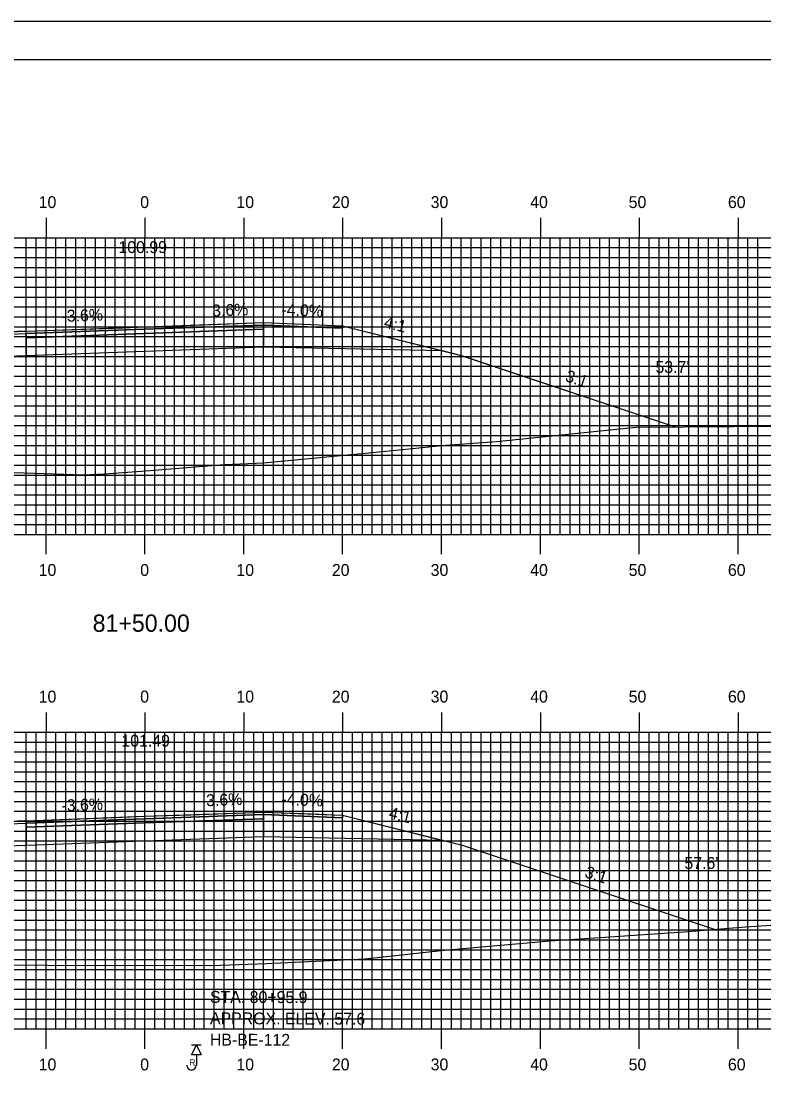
# Model space of a CAD drawing. Extents: x 1762578 to 1762921, y 442591 to 442811.
# Drawn here: x 1762731.3 to 1762806.4, y 442702.5 to 442810.5 of the extents above; entities that cross this region are included whole.
import ezdxf

# ---------------------------------------------------------------- set-up
doc = ezdxf.new("R2010")
doc.units = 0
for name, color, linetype in [('ANNOTATION', 7, 'Continuous'), ('BORDER', 7, 'Continuous'), ('BORING - REFUSAL', 7, 'Continuous'), ('D_Roadway_Centerline', 7, 'Continuous'), ('D_Roadway_Centerline_Text', 7, 'Continuous'), ('D_Roadway_Edge_Shoulder', 7, 'Continuous'), ('D_Roadway_Edge_TW', 7, 'Continuous'), ('D_Roadway_Pavement', 7, 'Continuous'), ('D_Roadway_SlopeLines', 7, 'Continuous'), ('D_Roadway_SubGrade', 7, 'Continuous'), ('D_Text_Standard', 7, 'Continuous'), ('H_V ANNOTATION', 7, 'Continuous'), ('MAJOR', 7, 'Continuous'), ('MINOR', 7, 'Continuous'), ('PLOT BOUNDARY', 7, 'Continuous'), ('S_Roadway_Centerline', 7, 'Continuous')]:
    doc.layers.add(name, color=color, linetype=linetype)

msp = doc.modelspace()

# ---------------------------------------------------------------- linework, layer by layer
at = {"layer": 'BORDER'}
msp.add_lwpolyline([(1762594.18, 442596.67), (1762914.18, 442596.67), (1762914.18, 442806.67), (1762594.18, 442806.67)], close=True, dxfattribs=at)
at = {"layer": 'BORING - REFUSAL'}
for p, q in [((1762749.46, 442707.01), (1762748.5, 442707.01)), ((1762748.98, 442706.05), (1762748.98, 442704.99))]:
    msp.add_line(p, q, dxfattribs=at)
msp.add_lwpolyline([(1762748.98, 442707.01), (1762749.46, 442706.05), (1762748.5, 442706.05)], close=True, dxfattribs=at)
msp.add_arc((1762748.49, 442704.99), 0.485, 180, 0, dxfattribs=at)
at = {"layer": 'D_Roadway_Centerline'}
for points in [[(1762679.23, 442765.05), (1762679.24, 442765.05), (1762683.25, 442766.39), (1762711.78, 442775.9), (1762712.06, 442775.97), (1762712.25, 442776.02), (1762712.25, 442776.02), (1762719.64, 442777.87), (1762723.78, 442778.9), (1762725.57, 442778.97), (1762731.78, 442779.22), (1762741.55, 442779.57), (1762743.78, 442779.66), (1762743.78, 442779.66), (1762749.62, 442779.87), (1762755.78, 442780.09), (1762755.78, 442780.09), (1762763.78, 442779.77), (1762763.78, 442779.77), (1762772.96, 442777.47), (1762773.95, 442777.22), (1762775.78, 442776.77), (1762775.79, 442776.76), (1762797.43, 442769.55)], [(1762724.97, 442729.45), (1762731.78, 442729.72), (1762731.78, 442729.72), (1762739.96, 442730.02), (1762743.78, 442730.16), (1762743.78, 442730.16), (1762748.39, 442730.32), (1762755.78, 442730.59), (1762755.78, 442730.59), (1762759.75, 442730.43), (1762763.78, 442730.27), (1762763.78, 442730.27), (1762763.78, 442730.27), (1762768.03, 442729.2), (1762773.95, 442727.72), (1762773.95, 442727.72), (1762775.78, 442727.27), (1762775.78, 442727.27), (1762801.37, 442718.74)]]:
    msp.add_lwpolyline(points, dxfattribs=at)
at = {"layer": 'D_Roadway_Edge_Shoulder'}
for points in [[(1762755.78, 442780.09), (1762763.78, 442779.77), (1762763.78, 442779.52), (1762755.78, 442779.84)], [(1762731.78, 442779.22), (1762723.78, 442778.9), (1762723.78, 442778.65), (1762731.78, 442778.97)], [(1762731.78, 442729.72), (1762723.78, 442729.4), (1762723.78, 442729.15), (1762731.78, 442729.47)], [(1762755.78, 442730.59), (1762763.78, 442730.27), (1762763.78, 442730.02), (1762755.78, 442730.34)]]:
    msp.add_lwpolyline(points, close=True, dxfattribs=at)
at = {"layer": 'D_Roadway_Edge_TW'}
for points in [[(1762731.78, 442778.97), (1762731.78, 442779.22), (1762743.78, 442779.66), (1762755.78, 442780.09), (1762755.78, 442779.84), (1762743.78, 442779.41)], [(1762755.78, 442780.09), (1762755.78, 442780.09), (1762755.78, 442779.84), (1762755.78, 442779.84)], [(1762731.78, 442729.47), (1762731.78, 442729.72), (1762743.78, 442730.16), (1762755.78, 442730.59), (1762755.78, 442730.34), (1762743.78, 442729.91)], [(1762755.78, 442730.59), (1762755.78, 442730.59), (1762755.78, 442730.34), (1762755.78, 442730.34)]]:
    msp.add_lwpolyline(points, close=True, dxfattribs=at)
at = {"layer": 'D_Roadway_Pavement'}
for points in [[(1762731.78, 442778.56), (1762731.78, 442778.97), (1762743.78, 442779.41), (1762755.78, 442779.84), (1762755.78, 442779.42), (1762743.78, 442778.99)], [(1762755.78, 442779.84), (1762755.78, 442779.84), (1762755.78, 442779.42), (1762755.78, 442779.42)], [(1762731.78, 442729.06), (1762731.78, 442729.47), (1762743.78, 442729.91), (1762755.78, 442730.34), (1762755.78, 442729.92), (1762743.78, 442729.49)], [(1762755.78, 442730.34), (1762755.78, 442730.34), (1762755.78, 442729.92), (1762755.78, 442729.92)]]:
    msp.add_lwpolyline(points, close=True, dxfattribs=at)
for points in [[(1762755.78, 442779.84), (1762755.78, 442779.42)], [(1762755.78, 442779.84), (1762755.78, 442779.42)], [(1762755.78, 442779.84), (1762755.78, 442779.42)], [(1762755.78, 442730.34), (1762755.78, 442729.92)], [(1762755.78, 442730.34), (1762755.78, 442729.92)], [(1762755.78, 442730.34), (1762755.78, 442729.92)]]:
    msp.add_lwpolyline(points, dxfattribs=at)
at = {"layer": 'D_Roadway_SlopeLines'}
for points in [[(1762763.78, 442779.77), (1762775.78, 442776.77), (1762797.43, 442769.55)], [(1762763.78, 442730.27), (1762775.78, 442727.27), (1762801.37, 442718.74)]]:
    msp.add_lwpolyline(points, dxfattribs=at)
at = {"layer": 'D_Roadway_SubGrade'}
for points in [[(1762731.78, 442776.72), (1762731.78, 442778.56), (1762743.78, 442778.99), (1762755.78, 442779.42), (1762755.78, 442777.59), (1762743.78, 442777.16)], [(1762755.78, 442779.42), (1762755.78, 442779.84), (1762763.78, 442779.52), (1762763.78, 442779.77), (1762773.95, 442777.22), (1762755.78, 442777.59)], [(1762755.78, 442779.42), (1762755.78, 442779.42), (1762755.78, 442777.59), (1762755.78, 442777.59)], [(1762723.78, 442778.65), (1762731.78, 442778.97), (1762731.78, 442778.56), (1762731.78, 442776.72), (1762712.25, 442776.02), (1762723.78, 442778.9)], [(1762731.78, 442727.22), (1762731.78, 442729.06), (1762743.78, 442729.49), (1762755.78, 442729.92), (1762755.78, 442728.09), (1762743.78, 442727.66)], [(1762755.78, 442729.92), (1762755.78, 442730.34), (1762763.78, 442730.02), (1762763.78, 442730.27), (1762773.95, 442727.72), (1762755.78, 442728.09)], [(1762755.78, 442729.92), (1762755.78, 442729.92), (1762755.78, 442728.09), (1762755.78, 442728.09)], [(1762723.78, 442729.15), (1762731.78, 442729.47), (1762731.78, 442729.06), (1762731.78, 442727.22), (1762712.25, 442726.52), (1762723.78, 442729.4)]]:
    msp.add_lwpolyline(points, close=True, dxfattribs=at)
at = {"layer": 'MAJOR'}
for p, q in [((1762733.78, 442790.67), (1762733.78, 442788.67)), ((1762743.78, 442790.67), (1762743.78, 442788.67)), ((1762753.78, 442790.67), (1762753.78, 442788.67)), ((1762763.78, 442790.67), (1762763.78, 442788.67)), ((1762773.78, 442790.67), (1762773.78, 442788.67)), ((1762783.78, 442790.67), (1762783.78, 442788.67)), ((1762793.78, 442790.67), (1762793.78, 442788.67)), ((1762803.78, 442790.67), (1762803.78, 442788.67)), ((1762603.78, 442788.67), (1762883.78, 442788.67)), ((1762603.78, 442788.67), (1762883.78, 442788.67)), ((1762733.78, 442758.67), (1762733.78, 442788.67)), ((1762743.78, 442758.67), (1762743.78, 442788.67)), ((1762753.78, 442758.67), (1762753.78, 442788.67)), ((1762763.78, 442758.67), (1762763.78, 442788.67)), ((1762773.78, 442758.67), (1762773.78, 442788.67)), ((1762783.78, 442758.67), (1762783.78, 442788.67)), ((1762793.78, 442758.67), (1762793.78, 442788.67)), ((1762803.78, 442758.67), (1762803.78, 442788.67)), ((1762603.78, 442783.67), (1762883.78, 442783.67)), ((1762603.78, 442778.67), (1762883.78, 442778.67)), ((1762603.78, 442773.67), (1762883.78, 442773.67)), ((1762603.78, 442768.67), (1762883.78, 442768.67)), ((1762603.78, 442763.67), (1762883.78, 442763.67)), ((1762603.78, 442758.67), (1762883.78, 442758.67)), ((1762603.78, 442758.67), (1762883.78, 442758.67)), ((1762733.78, 442756.66), (1762733.78, 442758.67)), ((1762743.78, 442756.66), (1762743.78, 442758.67)), ((1762753.78, 442756.66), (1762753.78, 442758.67)), ((1762763.78, 442756.66), (1762763.78, 442758.67)), ((1762773.78, 442756.66), (1762773.78, 442758.67)), ((1762783.78, 442756.66), (1762783.78, 442758.67)), ((1762793.78, 442756.66), (1762793.78, 442758.67)), ((1762803.78, 442756.66), (1762803.78, 442758.67)), ((1762733.78, 442740.67), (1762733.78, 442738.67)), ((1762743.78, 442740.67), (1762743.78, 442738.67)), ((1762753.78, 442740.67), (1762753.78, 442738.67)), ((1762763.78, 442740.67), (1762763.78, 442738.67)), ((1762773.78, 442740.67), (1762773.78, 442738.67)), ((1762783.78, 442740.67), (1762783.78, 442738.67)), ((1762793.78, 442740.67), (1762793.78, 442738.67)), ((1762803.78, 442740.67), (1762803.78, 442738.67)), ((1762603.78, 442738.67), (1762883.78, 442738.67)), ((1762603.78, 442738.67), (1762883.78, 442738.67)), ((1762733.78, 442708.67), (1762733.78, 442738.67)), ((1762743.78, 442708.67), (1762743.78, 442738.67)), ((1762753.78, 442708.67), (1762753.78, 442738.67)), ((1762763.78, 442708.67), (1762763.78, 442738.67)), ((1762773.78, 442708.67), (1762773.78, 442738.67)), ((1762783.78, 442708.67), (1762783.78, 442738.67)), ((1762793.78, 442708.67), (1762793.78, 442738.67)), ((1762803.78, 442708.67), (1762803.78, 442738.67)), ((1762603.78, 442733.67), (1762883.78, 442733.67)), ((1762603.78, 442728.67), (1762883.78, 442728.67)), ((1762603.78, 442723.67), (1762883.78, 442723.67)), ((1762603.78, 442718.67), (1762883.78, 442718.67)), ((1762603.78, 442713.67), (1762883.78, 442713.67)), ((1762603.78, 442708.67), (1762883.78, 442708.67)), ((1762603.78, 442708.67), (1762883.78, 442708.67)), ((1762733.78, 442706.66), (1762733.78, 442708.67)), ((1762743.78, 442706.66), (1762743.78, 442708.67)), ((1762753.78, 442706.66), (1762753.78, 442708.67)), ((1762763.78, 442706.66), (1762763.78, 442708.67)), ((1762773.78, 442706.66), (1762773.78, 442708.67)), ((1762783.78, 442706.66), (1762783.78, 442708.67)), ((1762793.78, 442706.66), (1762793.78, 442708.67)), ((1762803.78, 442706.66), (1762803.78, 442708.67))]:
    msp.add_line(p, q, dxfattribs=at)
at = {"layer": 'MINOR'}
for p, q in [((1762731.78, 442758.67), (1762731.78, 442788.67)), ((1762732.78, 442758.67), (1762732.78, 442788.67)), ((1762734.78, 442758.67), (1762734.78, 442788.67)), ((1762735.78, 442758.67), (1762735.78, 442788.67)), ((1762736.78, 442758.67), (1762736.78, 442788.67)), ((1762737.78, 442758.67), (1762737.78, 442788.67)), ((1762738.78, 442758.67), (1762738.78, 442788.67)), ((1762739.78, 442758.67), (1762739.78, 442788.67)), ((1762740.78, 442758.67), (1762740.78, 442788.67)), ((1762741.78, 442758.67), (1762741.78, 442788.67)), ((1762742.78, 442758.67), (1762742.78, 442788.67)), ((1762744.78, 442758.67), (1762744.78, 442788.67)), ((1762745.78, 442758.67), (1762745.78, 442788.67)), ((1762746.78, 442758.67), (1762746.78, 442788.67)), ((1762747.78, 442758.67), (1762747.78, 442788.67)), ((1762748.78, 442758.67), (1762748.78, 442788.67)), ((1762749.78, 442758.67), (1762749.78, 442788.67)), ((1762750.78, 442758.67), (1762750.78, 442788.67)), ((1762751.78, 442758.67), (1762751.78, 442788.67)), ((1762752.78, 442758.67), (1762752.78, 442788.67)), ((1762754.78, 442758.67), (1762754.78, 442788.67)), ((1762755.78, 442758.67), (1762755.78, 442788.67)), ((1762756.78, 442758.67), (1762756.78, 442788.67)), ((1762757.78, 442758.67), (1762757.78, 442788.67)), ((1762758.78, 442758.67), (1762758.78, 442788.67)), ((1762759.78, 442758.67), (1762759.78, 442788.67)), ((1762760.78, 442758.67), (1762760.78, 442788.67)), ((1762761.78, 442758.67), (1762761.78, 442788.67)), ((1762762.78, 442758.67), (1762762.78, 442788.67)), ((1762764.78, 442758.67), (1762764.78, 442788.67)), ((1762765.78, 442758.67), (1762765.78, 442788.67)), ((1762766.78, 442758.67), (1762766.78, 442788.67)), ((1762767.78, 442758.67), (1762767.78, 442788.67)), ((1762768.78, 442758.67), (1762768.78, 442788.67)), ((1762769.78, 442758.67), (1762769.78, 442788.67)), ((1762770.78, 442758.67), (1762770.78, 442788.67)), ((1762771.78, 442758.67), (1762771.78, 442788.67)), ((1762772.78, 442758.67), (1762772.78, 442788.67)), ((1762774.78, 442758.67), (1762774.78, 442788.67)), ((1762775.78, 442758.67), (1762775.78, 442788.67)), ((1762776.78, 442758.67), (1762776.78, 442788.67)), ((1762777.78, 442758.67), (1762777.78, 442788.67)), ((1762778.78, 442758.67), (1762778.78, 442788.67)), ((1762779.78, 442758.67), (1762779.78, 442788.67)), ((1762780.78, 442758.67), (1762780.78, 442788.67)), ((1762781.78, 442758.67), (1762781.78, 442788.67)), ((1762782.78, 442758.67), (1762782.78, 442788.67)), ((1762784.78, 442758.67), (1762784.78, 442788.67)), ((1762785.78, 442758.67), (1762785.78, 442788.67)), ((1762786.78, 442758.67), (1762786.78, 442788.67)), ((1762787.78, 442758.67), (1762787.78, 442788.67)), ((1762788.78, 442758.67), (1762788.78, 442788.67)), ((1762789.78, 442758.67), (1762789.78, 442788.67)), ((1762790.78, 442758.67), (1762790.78, 442788.67)), ((1762791.78, 442758.67), (1762791.78, 442788.67)), ((1762792.78, 442758.67), (1762792.78, 442788.67)), ((1762794.78, 442758.67), (1762794.78, 442788.67)), ((1762795.78, 442758.67), (1762795.78, 442788.67)), ((1762796.78, 442758.67), (1762796.78, 442788.67)), ((1762797.78, 442758.67), (1762797.78, 442788.67)), ((1762798.78, 442758.67), (1762798.78, 442788.67)), ((1762799.78, 442758.67), (1762799.78, 442788.67)), ((1762800.78, 442758.67), (1762800.78, 442788.67)), ((1762801.78, 442758.67), (1762801.78, 442788.67)), ((1762802.78, 442758.67), (1762802.78, 442788.67)), ((1762804.78, 442758.67), (1762804.78, 442788.67)), ((1762805.78, 442758.67), (1762805.78, 442788.67)), ((1762603.78, 442787.67), (1762883.78, 442787.67)), ((1762603.78, 442786.67), (1762883.78, 442786.67)), ((1762603.78, 442785.67), (1762883.78, 442785.67)), ((1762603.78, 442784.67), (1762883.78, 442784.67)), ((1762603.78, 442782.67), (1762883.78, 442782.67)), ((1762603.78, 442781.67), (1762883.78, 442781.67)), ((1762603.78, 442780.67), (1762883.78, 442780.67)), ((1762603.78, 442779.67), (1762883.78, 442779.67)), ((1762603.78, 442777.67), (1762883.78, 442777.67)), ((1762603.78, 442776.67), (1762883.78, 442776.67)), ((1762603.78, 442775.67), (1762883.78, 442775.67)), ((1762603.78, 442774.67), (1762883.78, 442774.67)), ((1762603.78, 442772.67), (1762883.78, 442772.67)), ((1762603.78, 442771.67), (1762883.78, 442771.67)), ((1762603.78, 442770.67), (1762883.78, 442770.67)), ((1762603.78, 442769.67), (1762883.78, 442769.67)), ((1762603.78, 442767.67), (1762883.78, 442767.67)), ((1762603.78, 442766.67), (1762883.78, 442766.67)), ((1762603.78, 442765.67), (1762883.78, 442765.67)), ((1762603.78, 442764.67), (1762883.78, 442764.67)), ((1762603.78, 442762.67), (1762883.78, 442762.67)), ((1762603.78, 442761.67), (1762883.78, 442761.67)), ((1762603.78, 442760.67), (1762883.78, 442760.67)), ((1762603.78, 442759.67), (1762883.78, 442759.67)), ((1762731.78, 442708.67), (1762731.78, 442738.67)), ((1762732.78, 442708.67), (1762732.78, 442738.67)), ((1762734.78, 442708.67), (1762734.78, 442738.67)), ((1762735.78, 442708.67), (1762735.78, 442738.67)), ((1762736.78, 442708.67), (1762736.78, 442738.67)), ((1762737.78, 442708.67), (1762737.78, 442738.67)), ((1762738.78, 442708.67), (1762738.78, 442738.67)), ((1762739.78, 442708.67), (1762739.78, 442738.67)), ((1762740.78, 442708.67), (1762740.78, 442738.67)), ((1762741.78, 442708.67), (1762741.78, 442738.67)), ((1762742.78, 442708.67), (1762742.78, 442738.67)), ((1762744.78, 442708.67), (1762744.78, 442738.67)), ((1762745.78, 442708.67), (1762745.78, 442738.67)), ((1762746.78, 442708.67), (1762746.78, 442738.67)), ((1762747.78, 442708.67), (1762747.78, 442738.67)), ((1762748.78, 442708.67), (1762748.78, 442738.67)), ((1762749.78, 442708.67), (1762749.78, 442738.67)), ((1762750.78, 442708.67), (1762750.78, 442738.67)), ((1762751.78, 442708.67), (1762751.78, 442738.67)), ((1762752.78, 442708.67), (1762752.78, 442738.67)), ((1762754.78, 442708.67), (1762754.78, 442738.67)), ((1762755.78, 442708.67), (1762755.78, 442738.67)), ((1762756.78, 442708.67), (1762756.78, 442738.67)), ((1762757.78, 442708.67), (1762757.78, 442738.67)), ((1762758.78, 442708.67), (1762758.78, 442738.67)), ((1762759.78, 442708.67), (1762759.78, 442738.67)), ((1762760.78, 442708.67), (1762760.78, 442738.67)), ((1762761.78, 442708.67), (1762761.78, 442738.67)), ((1762762.78, 442708.67), (1762762.78, 442738.67)), ((1762764.78, 442708.67), (1762764.78, 442738.67)), ((1762765.78, 442708.67), (1762765.78, 442738.67)), ((1762766.78, 442708.67), (1762766.78, 442738.67)), ((1762767.78, 442708.67), (1762767.78, 442738.67)), ((1762768.78, 442708.67), (1762768.78, 442738.67)), ((1762769.78, 442708.67), (1762769.78, 442738.67)), ((1762770.78, 442708.67), (1762770.78, 442738.67)), ((1762771.78, 442708.67), (1762771.78, 442738.67)), ((1762772.78, 442708.67), (1762772.78, 442738.67)), ((1762774.78, 442708.67), (1762774.78, 442738.67)), ((1762775.78, 442708.67), (1762775.78, 442738.67)), ((1762776.78, 442708.67), (1762776.78, 442738.67)), ((1762777.78, 442708.67), (1762777.78, 442738.67)), ((1762778.78, 442708.67), (1762778.78, 442738.67)), ((1762779.78, 442708.67), (1762779.78, 442738.67)), ((1762780.78, 442708.67), (1762780.78, 442738.67)), ((1762781.78, 442708.67), (1762781.78, 442738.67)), ((1762782.78, 442708.67), (1762782.78, 442738.67)), ((1762784.78, 442708.67), (1762784.78, 442738.67)), ((1762785.78, 442708.67), (1762785.78, 442738.67)), ((1762786.78, 442708.67), (1762786.78, 442738.67)), ((1762787.78, 442708.67), (1762787.78, 442738.67)), ((1762788.78, 442708.67), (1762788.78, 442738.67)), ((1762789.78, 442708.67), (1762789.78, 442738.67)), ((1762790.78, 442708.67), (1762790.78, 442738.67)), ((1762791.78, 442708.67), (1762791.78, 442738.67)), ((1762792.78, 442708.67), (1762792.78, 442738.67)), ((1762794.78, 442708.67), (1762794.78, 442738.67)), ((1762795.78, 442708.67), (1762795.78, 442738.67)), ((1762796.78, 442708.67), (1762796.78, 442738.67)), ((1762797.78, 442708.67), (1762797.78, 442738.67)), ((1762798.78, 442708.67), (1762798.78, 442738.67)), ((1762799.78, 442708.67), (1762799.78, 442738.67)), ((1762800.78, 442708.67), (1762800.78, 442738.67)), ((1762801.78, 442708.67), (1762801.78, 442738.67)), ((1762802.78, 442708.67), (1762802.78, 442738.67)), ((1762804.78, 442708.67), (1762804.78, 442738.67)), ((1762805.78, 442708.67), (1762805.78, 442738.67)), ((1762603.78, 442737.67), (1762883.78, 442737.67)), ((1762603.78, 442736.67), (1762883.78, 442736.67)), ((1762603.78, 442735.67), (1762883.78, 442735.67)), ((1762603.78, 442734.67), (1762883.78, 442734.67)), ((1762603.78, 442732.67), (1762883.78, 442732.67)), ((1762603.78, 442731.67), (1762883.78, 442731.67)), ((1762603.78, 442730.67), (1762883.78, 442730.67)), ((1762603.78, 442729.67), (1762883.78, 442729.67)), ((1762603.78, 442727.67), (1762883.78, 442727.67)), ((1762603.78, 442726.67), (1762883.78, 442726.67)), ((1762603.78, 442725.67), (1762883.78, 442725.67)), ((1762603.78, 442724.67), (1762883.78, 442724.67)), ((1762603.78, 442722.67), (1762883.78, 442722.67)), ((1762603.78, 442721.67), (1762883.78, 442721.67)), ((1762603.78, 442720.67), (1762883.78, 442720.67)), ((1762603.78, 442719.67), (1762883.78, 442719.67)), ((1762603.78, 442717.67), (1762883.78, 442717.67)), ((1762603.78, 442716.67), (1762883.78, 442716.67)), ((1762603.78, 442715.67), (1762883.78, 442715.67)), ((1762603.78, 442714.67), (1762883.78, 442714.67)), ((1762603.78, 442712.67), (1762883.78, 442712.67)), ((1762603.78, 442711.67), (1762883.78, 442711.67)), ((1762603.78, 442710.67), (1762883.78, 442710.67)), ((1762603.78, 442709.67), (1762883.78, 442709.67))]:
    msp.add_line(p, q, dxfattribs=at)
at = {"layer": 'PLOT BOUNDARY'}
msp.add_lwpolyline([(1762577.99, 442590.55), (1762917.99, 442590.55), (1762917.99, 442810.55), (1762577.99, 442810.55)], close=True, dxfattribs=at)
at = {"layer": 'S_Roadway_Centerline'}
for points in [[(1762655.76, 442765.13), (1762679.13, 442765.06), (1762680.21, 442765.02), (1762681.02, 442765.01), (1762684.95, 442765.03), (1762701.53, 442765.1), (1762712.45, 442765.21), (1762719.32, 442765.32), (1762728.54, 442764.98), (1762737.61, 442764.69), (1762739.67, 442764.8), (1762743.43, 442765.07), (1762751.81, 442765.72), (1762755.81, 442765.92), (1762768.16, 442767.1), (1762774.19, 442767.68), (1762779.34, 442768.07), (1762793.46, 442769.52), (1762808.18, 442769.62)], [(1762603.78, 442715.93), (1762615, 442715.29), (1762621.56, 442715.29), (1762639.34, 442715.45), (1762647.68, 442715.27), (1762661.87, 442715), (1762669.22, 442714.86), (1762671.41, 442714.79), (1762686.85, 442714.31), (1762690.37, 442714.22), (1762692.53, 442714.2), (1762703.22, 442714.51), (1762726.59, 442715.11), (1762729.34, 442715.14), (1762733.92, 442715.11), (1762750.45, 442715.09), (1762756.11, 442715.29), (1762766.02, 442715.74), (1762774.05, 442716.61), (1762784.72, 442717.56), (1762788.78, 442717.85), (1762798.29, 442718.48), (1762804.53, 442719), (1762810.77, 442719.38)]]:
    msp.add_lwpolyline(points, dxfattribs=at)

# ---------------------------------------------------------------- texts
at = {"layer": 'ANNOTATION'}
for s, rotation, p in [('-3.6%', 2.0618, (1762735.36, 442780.15)), ('3.6%', 2.0617, (1762750.6, 442780.7)), ('-4.0%', 357.7095, (1762757.57, 442780.82)), ('4:1', 345.9612, (1762767.88, 442779.6)), ('3:1', 341.5647, (1762786.21, 442774.2)), ('-3.6%', 2.0618, (1762735.36, 442730.65)), ('3.6%', 2.0617, (1762749.99, 442731.18)), ('-4.0%', 357.7094, (1762757.57, 442731.32)), ('4:1', 345.9614, (1762768.37, 442729.98)), ('3:1', 341.5648, (1762788.18, 442724.04))]:
    msp.add_text(s, height=1.2, rotation=rotation, dxfattribs=at).set_placement(p)
at = {"layer": 'BORING - REFUSAL'}
for s, p in [('STA. 80+95.9', (1762750.36, 442711.3)), ('APPROX. ELEV. 57.6', (1762750.36, 442709.14)), ('HB-BE-112', (1762750.35, 442706.98))]:
    msp.add_text(s, height=1.2, rotation=359.8142, dxfattribs=at).set_placement(p)
msp.add_text('R', height=0.64, dxfattribs=at).set_placement((1762748.27, 442704.94))
at = {"layer": 'D_Roadway_Centerline'}
for s, p in [('C', (1762743.77, 442779.66)), ('L', (1762743.78, 442779.65)), ('C', (1762743.77, 442730.16)), ('L', (1762743.78, 442730.15))]:
    msp.add_text(s, height=0.0146, dxfattribs=at).set_placement(p)
at = {"layer": 'D_Roadway_Centerline_Text'}
for s, p in [('100.99', (1762741.1, 442787.12)), ('101.49', (1762741.4, 442737.21))]:
    msp.add_text(s, height=1.2, dxfattribs=at).set_placement(p)
at = {"layer": 'D_Text_Standard'}
for s, p in [("53.7'", (1762795.42, 442775)), ("57.6'", (1762798.35, 442724.84))]:
    msp.add_text(s, height=1.2, dxfattribs=at).set_placement(p)
at = {"layer": 'H_V ANNOTATION'}
for s, height, p in [('10', 1.2, (1762733.03, 442791.67)), ('0', 1.2, (1762743.3, 442791.67)), ('10', 1.2, (1762753.03, 442791.67)), ('20', 1.2, (1762762.69, 442791.67)), ('30', 1.2, (1762772.68, 442791.67)), ('40', 1.2, (1762782.75, 442791.67)), ('50', 1.2, (1762792.71, 442791.67)), ('60', 1.2, (1762802.75, 442791.67)), ('10', 1.2, (1762733.03, 442754.47)), ('0', 1.2, (1762743.3, 442754.47)), ('10', 1.2, (1762753.03, 442754.47)), ('20', 1.2, (1762762.69, 442754.47)), ('30', 1.2, (1762772.68, 442754.47)), ('40', 1.2, (1762782.75, 442754.47)), ('50', 1.2, (1762792.71, 442754.47)), ('60', 1.2, (1762802.75, 442754.47)), ('81+50.00', 1.75, (1762738.49, 442748.82)), ('10', 1.2, (1762733.03, 442741.67)), ('0', 1.2, (1762743.3, 442741.67)), ('10', 1.2, (1762753.03, 442741.67)), ('20', 1.2, (1762762.69, 442741.67)), ('30', 1.2, (1762772.68, 442741.67)), ('40', 1.2, (1762782.75, 442741.67)), ('50', 1.2, (1762792.71, 442741.67)), ('60', 1.2, (1762802.75, 442741.67)), ('10', 1.2, (1762733.03, 442704.47)), ('0', 1.2, (1762743.3, 442704.47)), ('10', 1.2, (1762753.03, 442704.47)), ('20', 1.2, (1762762.69, 442704.47)), ('30', 1.2, (1762772.68, 442704.47)), ('40', 1.2, (1762782.75, 442704.47)), ('50', 1.2, (1762792.71, 442704.47)), ('60', 1.2, (1762802.75, 442704.47))]:
    msp.add_text(s, height=height, dxfattribs=at).set_placement(p)

doc.saveas('drawing.dxf')
